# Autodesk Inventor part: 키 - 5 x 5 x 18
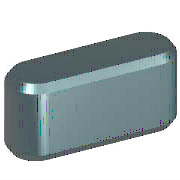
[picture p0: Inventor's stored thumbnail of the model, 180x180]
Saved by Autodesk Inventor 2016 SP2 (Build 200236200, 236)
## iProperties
Created: 2012-02
Part Number: 키 - 5 x 5 x 18
Material: 강철, 연강
Description: 키 및 해당 키홈
Document SubType Name: Modeling
Standard: KS B 1311
Designer: mduedu
Standards Organization: KS
Language: ko-KR
Size Designation: 5 x 5 x 18
Categories: <MemberInstance><Categories><Category DisplayName="샤프트 부품" InternalName="7f7aeb1f-a693-4053-b835-cee3144e0d98" Mnemonic="SHFT"><Category DisplayName="키" Interna
Density: 7.86 g/cm^3
Mass: 3.27476 g
Surface Area: 3.57848 cm^2
Volume: 0.416636 cm^3
Appearance: 파란색 - 벽 페인트 - 광택
IsCustomPart: 1
Author: mduedu
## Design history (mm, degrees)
workplane "Work Plane1"
workplane "Work Plane2"
sketch "스케치1"
  geometry: L1 (2.5, 2.5)-(15.5, 2.5); L2 (15.5, -2.5)-(2.5, -2.5); L3 (0, 9.4)-(0, -7.4) reference; L4 (-5, 0)-(30, 0) reference; L5 (18, 0)-(18, 7); A1 r 2.5 centre (2.5, 0) between (2.5, 2.5) and (2.5, -2.5); A2 r 2.5 centre (15.5, 0) between (15.5, -2.5) and (15.5, 2.5)
  constraints: 6 end point, 5 point on circle, 4 tangent, 3 point on line, 2 centre point, 1 horizontal, 1 parallel, 1 perpendicular
  dimensions: "d0" = 2.5 radius of A1 (= 0.5 x PB); "d13" = 2.5 radius of A2 (= 0.5 x PB); "d14" = 18 distance between parallel lines of L5 L3 (= NLG)
extrude "본체1" new body sketch "스케치1" taper "d3" = 0 deg; stored distance "d4" = 10
workplane "Work Plane3"
body "Solid1"
chamfer "모따기1" distance "d8" = 0.4 (= PHH); stored, may be unused: second distance "d9" = 0.4 (= PHH), angle "d15" = 45 deg
other parameters: "d1" = -3 (= -PNT), "d2" = 2 (= PH - PNT), "NLG" = 18 [user parameter; used in 3 equation terms], "PB" = 5 [user parameter; used in 2 equation terms], "PNT" = 3 [user parameter; used in 2 equation terms], "PH" = 5 [user parameter; used in 1 equation term], "PHH" = 0.4 [user parameter; used in 2 equation terms], "d10" = 0, "d16" = 0, "d17" = 0, "d18" = 0, "WDMIN" = 12 [user parameter], "PLB2" = 18 (= NLG) [user parameter], "WDMAX" = 17 [user parameter], "PLB1" = 18 (= NLG) [user parameter], "RR" = 0.16 [user parameter], "PUEB" = 2.3 [user parameter]
